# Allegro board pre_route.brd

Outline 330.2 x 304.8 mm; copper layers: TOP, L2_GND1, L3_IS1, L4_IS2, L5_PWR1, L6_IS3, L7_IS4, L8_GND2, L9_IS5, L10_IS6, L11_PWR2, L12_IS7, L13_IS8, L14_GND3, L15_IS9, L16_IS10, L17_PWR3, BOTTOM. Coordinates in mm from the lower left corner of the outline.
Outline path: 0,304.8 0,0 330.2,0 330.2,304.8 0,304.8

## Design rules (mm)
constraint set DEFAULT: min track width 0.127
net group BRIDGE_RXCLK_: nets BRIDGE_RXCLK_N BRIDGE_RXCLK_P
net group BRIDGE_TXCLK_: nets BRIDGE_TXCLK_N BRIDGE_TXCLK_P
net group DIFF_RX_DRSCLK_: nets DIFF_RX_DRSCLK_N DIFF_RX_DRSCLK_P
net group DIFF_RX_DRSTAT_0: nets DIFF_RX_DRSTAT_N0 DIFF_RX_DRSTAT_P0
net group DIFF_RX_DRSTAT_1: nets DIFF_RX_DRSTAT_N1 DIFF_RX_DRSTAT_P1
net group DIFF_RX_RCTL_: nets DIFF_RX_RCTL_N DIFF_RX_RCTL_P
net group DIFF_RX_RDCLK_: nets DIFF_RX_RDCLK_N DIFF_RX_RDCLK_P
net group DIFF_RX_RSTAT: nets DIFF_RX_RSTAT<0> DIFF_RX_RSTAT<1>
net group DIFF_TX_DTSCLK_: nets DIFF_TX_DTSCLK_N DIFF_TX_DTSCLK_P
net group DIFF_TX_DTSTAT_0: nets DIFF_TX_DTSTAT_N0 DIFF_TX_DTSTAT_P0
net group DIFF_TX_DTSTAT_1: nets DIFF_TX_DTSTAT_N1 DIFF_TX_DTSTAT_P1
net group DIFF_TX_TCTL_: nets DIFF_TX_TCTL_N DIFF_TX_TCTL_P
net group DIFF_TX_TDCLK_: nets DIFF_TX_TDCLK_N DIFF_TX_TDCLK_P
net group DIFF_TX_TSTAT: nets DIFF_TX_TSTAT<0> DIFF_TX_TSTAT<1>
net group DPA_RX_N: nets DPA_RX_N<0> DPA_RX_N<1>
net group DPA_RX_P: nets DPA_RX_P<0> DPA_RX_P<1>
net group DPA_TX_N: nets DPA_TX_N<0> DPA_TX_N<1>
net group DPA_TX_P: nets DPA_TX_P<0> DPA_TX_P<1>
net group DPACLK_IN_: nets DPACLK_IN_N DPACLK_IN_P
net group DPACLK_OUT_: nets DPACLK_OUT_N DPACLK_OUT_P
net group EXT_CLK_IN_: nets EXT_CLK_IN_N EXT_CLK_IN_P
net group LAN_RX: nets LAN_RXDN LAN_RXDP
net group LAN_TX: nets LAN_TXDN LAN_TXDP
net group PARALLELBUS_CLK_EN: nets PARALLELBUS_CLK_EN<0> PARALLELBUS_CLK_EN<1>
net group PARALLELBUS_ODT: nets PARALLELBUS_ODT<0> PARALLELBUS_ODT<1>
net group SMA_INPUT1_TO_SGX_: nets SMA_INPUT1_TO_SGX_N SMA_INPUT1_TO_SGX_P
net group SMA_INPUT2_TO_SGX_: nets SMA_INPUT2_TO_SGX_N SMA_INPUT2_TO_SGX_P
net group XCVR_RX_0C: nets XCVR_RX_N0C XCVR_RX_P0C
net group XCVR_RX_1C: nets XCVR_RX_N1C XCVR_RX_P1C
net group XCVR_RX_2C: nets XCVR_RX_N2C XCVR_RX_P2C
net group XCVR_RX_3C: nets XCVR_RX_N3C XCVR_RX_P3C
net group XCVR_RX_8C: nets XCVR_RX_N8C XCVR_RX_P8C
net group XCVR_RX_9C: nets XCVR_RX_N9C XCVR_RX_P9C
net group XCVR_RX_10C: nets XCVR_RX_N10C XCVR_RX_P10C
net group XCVR_RX_11C: nets XCVR_RX_N11C XCVR_RX_P11C
net group XCVR_RX_16C: nets XCVR_RX_N16C XCVR_RX_P16C
net group XCVR_RX_17C: nets XCVR_RX_N17C XCVR_RX_P17C
net group XCVR_RX_18C: nets XCVR_RX_N18C XCVR_RX_P18C
net group XCVR_RX_19C: nets XCVR_RX_N19C XCVR_RX_P19C
net group XTAL1_SGX_: nets XTAL1_SGX_N XTAL1_SGX_P
net group XTAL1_STX_: nets XTAL1_STX_N XTAL1_STX_P
net group XTAL2_SGX_: nets XTAL2_SGX_N XTAL2_SGX_P
net group XTAL2_STX_: nets XTAL2_STX_N XTAL2_STX_P
net group BRIDGE_RX_N: nets BRIDGE_RX_N<0> BRIDGE_RX_N<1> BRIDGE_RX_N<2> BRIDGE_RX_N<3> BRIDGE_RX_N<4> BRIDGE_RX_N<5> BRIDGE_RX_N<6> BRIDGE_RX_N<7> BRIDGE_RX_N<8> BRIDGE_RX_N<9> BRIDGE_RX_N<10> BRIDGE_RX_N<11> BRIDGE_RX_N<12> BRIDGE_RX_N<13> BRIDGE_RX_N<14> BRIDGE_RX_N<15>
net group BRIDGE_RX_P: nets BRIDGE_RX_P<0> BRIDGE_RX_P<1> BRIDGE_RX_P<2> BRIDGE_RX_P<3> BRIDGE_RX_P<4> BRIDGE_RX_P<5> BRIDGE_RX_P<6> BRIDGE_RX_P<7> BRIDGE_RX_P<8> BRIDGE_RX_P<9> BRIDGE_RX_P<10> BRIDGE_RX_P<11> BRIDGE_RX_P<12> BRIDGE_RX_P<13> BRIDGE_RX_P<14> BRIDGE_RX_P<15>
net group BRIDGE_TX_N: nets BRIDGE_TX_N<0> BRIDGE_TX_N<1> BRIDGE_TX_N<2> BRIDGE_TX_N<3> BRIDGE_TX_N<4> BRIDGE_TX_N<5> BRIDGE_TX_N<6> BRIDGE_TX_N<7> BRIDGE_TX_N<8> BRIDGE_TX_N<9> BRIDGE_TX_N<10> BRIDGE_TX_N<11> BRIDGE_TX_N<12> BRIDGE_TX_N<13> BRIDGE_TX_N<14> BRIDGE_TX_N<15>
net group BRIDGE_TX_P: nets BRIDGE_TX_P<0> BRIDGE_TX_P<1> BRIDGE_TX_P<2> BRIDGE_TX_P<3> BRIDGE_TX_P<4> BRIDGE_TX_P<5> BRIDGE_TX_P<6> BRIDGE_TX_P<7> BRIDGE_TX_P<8> BRIDGE_TX_P<9> BRIDGE_TX_P<10> BRIDGE_TX_P<11> BRIDGE_TX_P<12> BRIDGE_TX_P<13> BRIDGE_TX_P<14> BRIDGE_TX_P<15>
net group DEV2_D: nets DEV2_D<0> DEV2_D<1> DEV2_D<2> DEV2_D<3> DEV2_D<4> DEV2_D<5> DEV2_D<6> DEV2_D<7>
net group DIFF_PH: nets DATA_GEN_CLK_INN DATA_GEN_CLK_INP DIVIDE_BY_20_LVPECL_OUT_N DIVIDE_BY_20_LVPECL_OUT_P XTAL1_SGX_INT_N XTAL1_SGX_INT_P XTAL1_STX_INT_N XTAL1_STX_INT_P XTAL1_TP_N XTAL1_TP_P XTAL2_SGX_INT_N XTAL2_SGX_INT_P XTAL2_STX_INT_N XTAL2_STX_INT_P XTAL2_TP_N XTAL2_TP_P
net group DIFF_RX_N: nets DIFF_RX_N<0> DIFF_RX_N<1> DIFF_RX_N<2> DIFF_RX_N<3> DIFF_RX_N<4> DIFF_RX_N<5> DIFF_RX_N<6> DIFF_RX_N<7> DIFF_RX_N<8> DIFF_RX_N<9> DIFF_RX_N<10> DIFF_RX_N<11> DIFF_RX_N<12> DIFF_RX_N<13> DIFF_RX_N<14> DIFF_RX_N<15>
net group DIFF_RX_P: nets DIFF_RX_P<0> DIFF_RX_P<1> DIFF_RX_P<2> DIFF_RX_P<3> DIFF_RX_P<4> DIFF_RX_P<5> DIFF_RX_P<6> DIFF_RX_P<7> DIFF_RX_P<8> DIFF_RX_P<9> DIFF_RX_P<10> DIFF_RX_P<11> DIFF_RX_P<12> DIFF_RX_P<13> DIFF_RX_P<14> DIFF_RX_P<15>
net group DIFF_TX_N: nets DIFF_TX_N<0> DIFF_TX_N<1> DIFF_TX_N<2> DIFF_TX_N<3> DIFF_TX_N<4> DIFF_TX_N<5> DIFF_TX_N<6> DIFF_TX_N<7> DIFF_TX_N<8> DIFF_TX_N<9> DIFF_TX_N<10> DIFF_TX_N<11> DIFF_TX_N<12> DIFF_TX_N<13> DIFF_TX_N<14> DIFF_TX_N<15>
net group DIFF_TX_P: nets DIFF_TX_P<0> DIFF_TX_P<1> DIFF_TX_P<2> DIFF_TX_P<3> DIFF_TX_P<4> DIFF_TX_P<5> DIFF_TX_P<6> DIFF_TX_P<7> DIFF_TX_P<8> DIFF_TX_P<9> DIFF_TX_P<10> DIFF_TX_P<11> DIFF_TX_P<12> DIFF_TX_P<13> DIFF_TX_P<14> DIFF_TX_P<15>
net group FLASH_A: nets FLASH_A<0> FLASH_A<1> FLASH_A<2> FLASH_A<3> FLASH_A<4> FLASH_A<5> FLASH_A<6> FLASH_A<7> FLASH_A<8> FLASH_A<9> FLASH_A<10> FLASH_A<11> FLASH_A<12> FLASH_A<13> FLASH_A<14> FLASH_A<15> FLASH_A<16> FLASH_A<17> FLASH_A<18> FLASH_A<19> FLASH_A<20> FLASH_A<21>
net group FLASH_D: nets FLASH_D<0> FLASH_D<1> FLASH_D<2> FLASH_D<3> FLASH_D<4> FLASH_D<5> FLASH_D<6> FLASH_D<7> FLASH_D<8> FLASH_D<9> FLASH_D<10> FLASH_D<11> FLASH_D<12> FLASH_D<13> FLASH_D<14> FLASH_D<15>
net group GX_DIP: nets GX_DIP<0> GX_DIP<1> GX_DIP<2> GX_DIP<3> GX_DIP<4> GX_DIP<5> GX_DIP<6> GX_DIP<7>
net group GX_FLASH_A: nets GX_FLASH_A<0> GX_FLASH_A<1> GX_FLASH_A<2> GX_FLASH_A<3> GX_FLASH_A<4> GX_FLASH_A<5> GX_FLASH_A<6> GX_FLASH_A<7> GX_FLASH_A<8> GX_FLASH_A<9> GX_FLASH_A<10> GX_FLASH_A<11> GX_FLASH_A<12> GX_FLASH_A<13> GX_FLASH_A<14> GX_FLASH_A<15> GX_FLASH_A<16> GX_FLASH_A<17> GX_FLASH_A<18> GX_FLASH_A<19> GX_FLASH_A<20>
net group GX_FLASH_D: nets GX_FLASH_D<0> GX_FLASH_D<1> GX_FLASH_D<2> GX_FLASH_D<3> GX_FLASH_D<4> GX_FLASH_D<5> GX_FLASH_D<6> GX_FLASH_D<7> GX_FLASH_D<8> GX_FLASH_D<9> GX_FLASH_D<10> GX_FLASH_D<11> GX_FLASH_D<12> GX_FLASH_D<13> GX_FLASH_D<14> GX_FLASH_D<15>
net group GX_HEADER: nets GX_HEADER<0> GX_HEADER<1> GX_HEADER<2> GX_HEADER<3> GX_HEADER<4> GX_HEADER<5> GX_HEADER<6> GX_HEADER<7> GX_HEADER<8> GX_HEADER<9> GX_HEADER<10> GX_HEADER<11> GX_HEADER<12> GX_HEADER<13> GX_HEADER<14> GX_HEADER<15> GX_HEADER<16> GX_HEADER<17> GX_HEADER<18> GX_HEADER<19>
net group GX_LED: nets GX_LED<0> GX_LED<1> GX_LED<2> GX_LED<3> GX_LED<4> GX_LED<5>
net group GX_MICTOR_EP_: nets GX_MICTOR_EP_<0> GX_MICTOR_EP_<1> GX_MICTOR_EP_<2> GX_MICTOR_EP_<3> GX_MICTOR_EP_<4> GX_MICTOR_EP_<5> GX_MICTOR_EP_<6> GX_MICTOR_EP_<7> GX_MICTOR_EP_<8> GX_MICTOR_EP_<9> GX_MICTOR_EP_<10> GX_MICTOR_EP_<11> GX_MICTOR_EP_<12> GX_MICTOR_EP_<13> GX_MICTOR_EP_<14> GX_MICTOR_EP_<15>
net group GX_MICTOR_OP_: nets GX_MICTOR_OP_<0> GX_MICTOR_OP_<1> GX_MICTOR_OP_<2> GX_MICTOR_OP_<3> GX_MICTOR_OP_<4> GX_MICTOR_OP_<5> GX_MICTOR_OP_<6> GX_MICTOR_OP_<7> GX_MICTOR_OP_<8> GX_MICTOR_OP_<9> GX_MICTOR_OP_<10> GX_MICTOR_OP_<11> GX_MICTOR_OP_<12> GX_MICTOR_OP_<13> GX_MICTOR_OP_<14> GX_MICTOR_OP_<15>
net group GX_PB: nets GX_PB<0> GX_PB<1> GX_PB<2> GX_PB<3>
net group GX_RECOV_CLK: nets GX_RECOV_CLK<0> GX_RECOV_CLK<1> GX_RECOV_CLK<2> GX_RECOV_CLK<3> GX_RECOV_CLK<4>
net group GXPGM: nets GXPGM<0> GXPGM<1> GXPGM<2>
net group LAN_A: nets LAN_A<0> LAN_A<1> LAN_A<2> LAN_A<3> LAN_A<4> LAN_A<5> LAN_A<6> LAN_A<7> LAN_A<8> LAN_A<9> LAN_A<10> LAN_A<11> LAN_A<12> LAN_A<13> LAN_A<14>
net group LAN_BEN: nets LAN_BEN<0> LAN_BEN<1> LAN_BEN<2> LAN_BEN<3>
net group LAN_D: nets LAN_D<0> LAN_D<1> LAN_D<2> LAN_D<3> LAN_D<4> LAN_D<5> LAN_D<6> LAN_D<7> LAN_D<8> LAN_D<9> LAN_D<10> LAN_D<11> LAN_D<12> LAN_D<13> LAN_D<14> LAN_D<15> LAN_D<16> LAN_D<17> LAN_D<18> LAN_D<19> LAN_D<20> LAN_D<21> LAN_D<22> LAN_D<23> LAN_D<24> LAN_D<25> LAN_D<26> LAN_D<27> LAN_D<28> LAN_D<29> LAN_D<30> LAN_D<31>
net group PARALLELBUS_ADDR: nets PARALLELBUS_ADDR<0> PARALLELBUS_ADDR<1> PARALLELBUS_ADDR<2> PARALLELBUS_ADDR<3> PARALLELBUS_ADDR<4> PARALLELBUS_ADDR<5> PARALLELBUS_ADDR<6> PARALLELBUS_ADDR<7> PARALLELBUS_ADDR<8> PARALLELBUS_ADDR<9> PARALLELBUS_ADDR<10> PARALLELBUS_ADDR<11> PARALLELBUS_ADDR<12> PARALLELBUS_ADDR<13> PARALLELBUS_ADDR<14> PARALLELBUS_ADDR<15>
net group PARALLELBUS_BA: nets PARALLELBUS_BA<0> PARALLELBUS_BA<1> PARALLELBUS_BA<2>
net group PARALLELBUS_CB: nets PARALLELBUS_CB<0> PARALLELBUS_CB<1> PARALLELBUS_CB<2> PARALLELBUS_CB<3> PARALLELBUS_CB<4> PARALLELBUS_CB<5> PARALLELBUS_CB<6> PARALLELBUS_CB<7>
net group PARALLELBUS_DATA: nets PARALLELBUS_DATA<0> PARALLELBUS_DATA<1> PARALLELBUS_DATA<2> PARALLELBUS_DATA<3> PARALLELBUS_DATA<4> PARALLELBUS_DATA<5> PARALLELBUS_DATA<6> PARALLELBUS_DATA<7> PARALLELBUS_DATA<8> PARALLELBUS_DATA<9> PARALLELBUS_DATA<10> PARALLELBUS_DATA<11> PARALLELBUS_DATA<12> PARALLELBUS_DATA<13> PARALLELBUS_DATA<14> PARALLELBUS_DATA<15> PARALLELBUS_DATA<16> PARALLELBUS_DATA<17> PARALLELBUS_DATA<18> PARALLELBUS_DATA<19> PARALLELBUS_DATA<20> PARALLELBUS_DATA<21> PARALLELBUS_DATA<22> PARALLELBUS_DATA<23> PARALLELBUS_DATA<24> PARALLELBUS_DATA<25> PARALLELBUS_DATA<26> PARALLELBUS_DATA<27> PARALLELBUS_DATA<28> PARALLELBUS_DATA<29> PARALLELBUS_DATA<30> PARALLELBUS_DATA<31> PARALLELBUS_DATA<32> PARALLELBUS_DATA<33> PARALLELBUS_DATA<34> PARALLELBUS_DATA<35> PARALLELBUS_DATA<36> PARALLELBUS_DATA<37> PARALLELBUS_DATA<38> PARALLELBUS_DATA<39> PARALLELBUS_DATA<40> PARALLELBUS_DATA<41> PARALLELBUS_DATA<42> PARALLELBUS_DATA<43> PARALLELBUS_DATA<44> PARALLELBUS_DATA<45> PARALLELBUS_DATA<46> PARALLELBUS_DATA<47> PARALLELBUS_DATA<48> PARALLELBUS_DATA<49> PARALLELBUS_DATA<50> PARALLELBUS_DATA<51> PARALLELBUS_DATA<52> PARALLELBUS_DATA<53> PARALLELBUS_DATA<54> PARALLELBUS_DATA<55> PARALLELBUS_DATA<56> PARALLELBUS_DATA<57> PARALLELBUS_DATA<58> PARALLELBUS_DATA<59> PARALLELBUS_DATA<60> PARALLELBUS_DATA<61> PARALLELBUS_DATA<62> PARALLELBUS_DATA<63>
net group PARALLELBUS_DM: nets PARALLELBUS_DM<0> PARALLELBUS_DM<1> PARALLELBUS_DM<2> PARALLELBUS_DM<3> PARALLELBUS_DM<4> PARALLELBUS_DM<5> PARALLELBUS_DM<6> PARALLELBUS_DM<7> PARALLELBUS_DM<8>
net group PARALLELBUS_STROBE: nets PARALLELBUS_STROBE<0> PARALLELBUS_STROBE<1> PARALLELBUS_STROBE<2> PARALLELBUS_STROBE<3> PARALLELBUS_STROBE<4> PARALLELBUS_STROBE<5> PARALLELBUS_STROBE<6> PARALLELBUS_STROBE<7>
net group PMC_AD: nets PMC_AD<0> PMC_AD<1> PMC_AD<2> PMC_AD<3> PMC_AD<4> PMC_AD<5> PMC_AD<6> PMC_AD<7> PMC_AD<8> PMC_AD<9> PMC_AD<10> PMC_AD<11> PMC_AD<12> PMC_AD<13> PMC_AD<14> PMC_AD<15> PMC_AD<16> PMC_AD<17> PMC_AD<18> PMC_AD<19> PMC_AD<20> PMC_AD<21> PMC_AD<22> PMC_AD<23> PMC_AD<24> PMC_AD<25> PMC_AD<26> PMC_AD<27> PMC_AD<28> PMC_AD<29> PMC_AD<30> PMC_AD<31>
net group PMC_BUSMODEN: nets PMC_BUSMODEN<1> PMC_BUSMODEN<2> PMC_BUSMODEN<3> PMC_BUSMODEN<4>
net group PMC_C_BEN: nets PMC_C_BEN<0> PMC_C_BEN<1> PMC_C_BEN<2> PMC_C_BEN<3>
net group PWR_PH: nets 1.5V_A_INT 1.5V_GX_INT 1.5V_PLL 1.5V_PLL_B 1.5V_S_INT 1.5V_XCVR 1.5V_XCVR5 1.25V 2.5V 2.5V_DDR_VDD 2.5V_GX_IO 2.5V_OUT 2.5V_REG_IN 3.3V 3.3V_CLK1 3.3V_CLK2 3.3V_CLK3 3.3V_DIV 3.3V_EXT_CLK 3.3V_FAN_OUT 3.3V_LAN 3.3V_RS232 3.3V_S_IO 3.3V_S_IOB 3.3V_XCVR_CLKS 3.3VM 5VM 12VM -12VM -48V_IN -48V_ONN -48V_PWR BUS_CONV_5V GND GND_HSSI GND_PLL GND_RTN VCCA VCCQP
net group Q_SCRUZ_IO: nets Q_SCRUZ_IO<0> Q_SCRUZ_IO<1> Q_SCRUZ_IO<2> Q_SCRUZ_IO<3> Q_SCRUZ_IO<4> Q_SCRUZ_IO<5> Q_SCRUZ_IO<6> Q_SCRUZ_IO<7> Q_SCRUZ_IO<8> Q_SCRUZ_IO<9> Q_SCRUZ_IO<10> Q_SCRUZ_IO<11> Q_SCRUZ_IO<12> Q_SCRUZ_IO<13> Q_SCRUZ_IO<14> Q_SCRUZ_IO<15> Q_SCRUZ_IO<16> Q_SCRUZ_IO<17> Q_SCRUZ_IO<18> Q_SCRUZ_IO<19> Q_SCRUZ_IO<20> Q_SCRUZ_IO<21> Q_SCRUZ_IO<22> Q_SCRUZ_IO<23> Q_SCRUZ_IO<24> Q_SCRUZ_IO<25> Q_SCRUZ_IO<26> Q_SCRUZ_IO<27> Q_SCRUZ_IO<28> Q_SCRUZ_IO<29> Q_SCRUZ_IO<30> Q_SCRUZ_IO<31> Q_SCRUZ_IO<32> Q_SCRUZ_IO<33> Q_SCRUZ_IO<34> Q_SCRUZ_IO<35> Q_SCRUZ_IO<36> Q_SCRUZ_IO<37> Q_SCRUZ_IO<38> Q_SCRUZ_IO<39>
net group S_DIP: nets S_DIP<0> S_DIP<1> S_DIP<2> S_DIP<3> S_DIP<4> S_DIP<5> S_DIP<6> S_DIP<7>
net group S_HEADER: nets S_HEADER<0> S_HEADER<1> S_HEADER<2> S_HEADER<3> S_HEADER<4> S_HEADER<5> S_HEADER<6> S_HEADER<7> S_HEADER<8> S_HEADER<9> S_HEADER<10> S_HEADER<11> S_HEADER<12> S_HEADER<13> S_HEADER<14> S_HEADER<15> S_HEADER<16> S_HEADER<17> S_HEADER<18> S_HEADER<19>
net group S_LED: nets S_LED<0> S_LED<1> S_LED<2> S_LED<3> S_LED<4> S_LED<5>
net group S_MICTOR_EP_: nets S_MICTOR_EP_<0> S_MICTOR_EP_<1> S_MICTOR_EP_<2> S_MICTOR_EP_<3> S_MICTOR_EP_<4> S_MICTOR_EP_<5> S_MICTOR_EP_<6> S_MICTOR_EP_<7> S_MICTOR_EP_<8> S_MICTOR_EP_<9> S_MICTOR_EP_<10> S_MICTOR_EP_<11> S_MICTOR_EP_<12> S_MICTOR_EP_<13> S_MICTOR_EP_<14> S_MICTOR_EP_<15>
net group S_MICTOR_OP_: nets S_MICTOR_OP_<0> S_MICTOR_OP_<1> S_MICTOR_OP_<2> S_MICTOR_OP_<3> S_MICTOR_OP_<4> S_MICTOR_OP_<5> S_MICTOR_OP_<6> S_MICTOR_OP_<7> S_MICTOR_OP_<8> S_MICTOR_OP_<9> S_MICTOR_OP_<10> S_MICTOR_OP_<11> S_MICTOR_OP_<12> S_MICTOR_OP_<13> S_MICTOR_OP_<14> S_MICTOR_OP_<15>
net group S_PB: nets S_PB<0> S_PB<1> S_PB<2> S_PB<3>
net group SCRUZ_IO: nets SCRUZ_IO<0> SCRUZ_IO<1> SCRUZ_IO<2> SCRUZ_IO<3> SCRUZ_IO<4> SCRUZ_IO<5> SCRUZ_IO<6> SCRUZ_IO<7> SCRUZ_IO<8> SCRUZ_IO<9> SCRUZ_IO<10> SCRUZ_IO<11> SCRUZ_IO<12> SCRUZ_IO<13> SCRUZ_IO<14> SCRUZ_IO<15> SCRUZ_IO<16> SCRUZ_IO<17> SCRUZ_IO<18> SCRUZ_IO<19> SCRUZ_IO<20> SCRUZ_IO<21> SCRUZ_IO<22> SCRUZ_IO<23> SCRUZ_IO<24> SCRUZ_IO<25> SCRUZ_IO<26> SCRUZ_IO<27> SCRUZ_IO<28> SCRUZ_IO<29> SCRUZ_IO<30> SCRUZ_IO<31> SCRUZ_IO<32> SCRUZ_IO<33> SCRUZ_IO<34> SCRUZ_IO<35> SCRUZ_IO<36> SCRUZ_IO<37> SCRUZ_IO<38> SCRUZ_IO<39>
net group SFP0_MOD_DEF4_: nets SFP0_MOD_DEF4_<0> SFP0_MOD_DEF4_<1> SFP0_MOD_DEF4_<2>
net group SFP1_MOD_DEF5_: nets SFP1_MOD_DEF5_<0> SFP1_MOD_DEF5_<1> SFP1_MOD_DEF5_<2>
net group SFP2_MOD_DEF6_: nets SFP2_MOD_DEF6_<0> SFP2_MOD_DEF6_<1> SFP2_MOD_DEF6_<2>
net group SFP3_MOD_DEF7_: nets SFP3_MOD_DEF7_<0> SFP3_MOD_DEF7_<1> SFP3_MOD_DEF7_<2>
net group XCVR_RX_N: nets XCVR_RX_N<0> XCVR_RX_N<1> XCVR_RX_N<2> XCVR_RX_N<3> XCVR_RX_N<4> XCVR_RX_N<5> XCVR_RX_N<6> XCVR_RX_N<7> XCVR_RX_N<8> XCVR_RX_N<9> XCVR_RX_N<10> XCVR_RX_N<11> XCVR_RX_N<12> XCVR_RX_N<13> XCVR_RX_N<14> XCVR_RX_N<15> XCVR_RX_N<16> XCVR_RX_N<17> XCVR_RX_N<18> XCVR_RX_N<19>
net group XCVR_RX_P: nets XCVR_RX_P<0> XCVR_RX_P<1> XCVR_RX_P<2> XCVR_RX_P<3> XCVR_RX_P<4> XCVR_RX_P<5> XCVR_RX_P<6> XCVR_RX_P<7> XCVR_RX_P<8> XCVR_RX_P<9> XCVR_RX_P<10> XCVR_RX_P<11> XCVR_RX_P<12> XCVR_RX_P<13> XCVR_RX_P<14> XCVR_RX_P<15> XCVR_RX_P<16> XCVR_RX_P<17> XCVR_RX_P<18> XCVR_RX_P<19>
net group XCVR_TX_N: nets XCVR_TX_N<0> XCVR_TX_N<1> XCVR_TX_N<2> XCVR_TX_N<3> XCVR_TX_N<4> XCVR_TX_N<5> XCVR_TX_N<6> XCVR_TX_N<7> XCVR_TX_N<8> XCVR_TX_N<9> XCVR_TX_N<10> XCVR_TX_N<11> XCVR_TX_N<12> XCVR_TX_N<13> XCVR_TX_N<14> XCVR_TX_N<15> XCVR_TX_N<16> XCVR_TX_N<17> XCVR_TX_N<18> XCVR_TX_N<19>
net group XCVR_TX_P: nets XCVR_TX_P<0> XCVR_TX_P<1> XCVR_TX_P<2> XCVR_TX_P<3> XCVR_TX_P<4> XCVR_TX_P<5> XCVR_TX_P<6> XCVR_TX_P<7> XCVR_TX_P<8> XCVR_TX_P<9> XCVR_TX_P<10> XCVR_TX_P<11> XCVR_TX_P<12> XCVR_TX_P<13> XCVR_TX_P<14> XCVR_TX_P<15> XCVR_TX_P<16> XCVR_TX_P<17> XCVR_TX_P<18> XCVR_TX_P<19>
net group XPAK_PRTAD: nets XPAK_PRTAD<0> XPAK_PRTAD<1> XPAK_PRTAD<2> XPAK_PRTAD<3> XPAK_PRTAD<4>
net group XPAK_VEND: nets XPAK_VEND<0> XPAK_VEND<1> XPAK_VEND<2> XPAK_VEND<3>

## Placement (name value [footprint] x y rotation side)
C1  0.01uf  [CAP_0402]  -102.35 126.37 0 top
C2  0.01uf  [CAP_0402]  -102.35 137.8 0 top
C3  0.01uf  [CAP_0402]  -102.35 149.23 0 top
C4  0.01uf  [CAP_0402]  -102.35 151.52 0 top
C5  0.01uf  [CAP_0402]  -102.35 153.8 0 top
C6  0.01uf  [CAP_0402]  -102.35 156.09 0 top
C7  0.01uf  [CAP_0402]  -102.35 158.38 0 top
C8  0.01uf  [CAP_0402]  -102.35 162.95 0 top
C9  10uf  [CAP_1206]  -70.12 156.4 0 top
C10  0.01uf  [CAP_0402]  -102.35 165.23 0 top
C11  0.01uf  [CAP_0402]  -102.35 167.52 0 top
C12  10uf  [CAPT_3528]  -55.19 31.98 0 top
C13  0.1uf  [CAP_0603]  -157.01 221.32 0 top
C14  10uf  [CAP_1206]  -70.12 182.84 0 top
C15  10uf  [CAP_1206]  -70.12 177.55 0 top
C16  0.1uf  [CAP_0603]  -157.01 192.07 0 top
C17  0.01uf  [CAP_0402]  -102.35 169.81 0 top
C18  0.01uf  [CAP_0402]  -102.35 172.09 0 top
C19  220uf  [CAPT_7343]  -84.03 68.71 0 top
C20  0.01uf  [CAP_0402]  -102.35 140.09 0 top
C21  0.01uf  [CAP_0402]  -102.35 142.37 0 top
C22  0.01uf  [CAP_0402]  -102.35 174.38 0 top
C23  0.01uf  [CAP_0402]  -102.35 176.66 0 top
C24  0.01uf  [CAP_0402]  -102.35 144.66 0 top
C25  0.01uf  [CAP_0402]  -102.35 146.95 0 top
C26  0.01uf  [CAP_0603]  -76.05 229.73 0 top
C27  0.01uf  [CAP_0603]  -76.05 200.48 0 top
C28  820pf  [CAP_SP]  -84.55 43.56 0 top
C29  0.01uf  [CAP_0402]  -102.35 178.95 0 top
C30  0.01uf  [CAP_0402]  -79.57 7.35 0 top
C31  0.01uf  [CAP_0402]  -79.57 5.06 0 top
C32  0.01uf  [CAP_0402]  -102.35 181.24 0 top
C33  0.01uf  [CAP_0603]  -76.05 131.02 0 top
C34  0.01uf  [CAP_0603]  -76.05 105.43 0 top
C35  0.01uf  [CAP_0603]  -76.05 87.15 0 top
C36  0.01uf  [CAP_0603]  -76.05 72.53 0 top
C37  0.01uf  [CAP_0603]  -76.05 61.56 0 top
C38  0.01uf  [CAP_0603]  -76.05 43.28 0 top
C39  0.01uf  [CAP_0603]  -76.05 17.69 0 top
C40  0.01uf  [CAP_0603]  -77.9 295.53 0 top
C41  2.2uf  [CAP_0805]  -70.02 245.08 0 top
C42  680uf  [CAP_SP]  -95.94 268.88 0 top
C43  0.01uf  [CAP_0603]  -77.9 258.98 0 top
C44  0.1uf  [CAP_0603]  -51.09 145.64 0 top
C45  0.1uf  [CAP_0603]  -51.09 138.33 0 top
C46  0.01uf  [CAP_0603]  -77.9 200.48 0 top
C47  2.2uf  [CAP_0805]  -70.02 208.09 0 top
C48  0.047uf  [CAP_1206]  -91.56 256.54 0 top
C49  0.01uf  [CAP_0603]  -77.9 156.61 0 top
C50  10uf  [CAPT_3528]  -55.19 27.67 0 top
C51  10uf  [CAPT_3528]  -55.19 23.35 0 top
C52  10uf  [CAPT_3528]  -55.19 19.03 0 top
C53  10uf  [CAPT_3528]  -55.19 14.71 0 top
C54  0.1uf  [CAP_0603]  -51.09 3.07 0 top
C55  0.1uf  [CAP_0603]  -52.94 291.88 0 top
C56  0.01uf  [CAP_0603]  -77.9 30.03 0 top
C57  680uf  [CAP_SP]  -95.94 249.19 0 top
C58  0.01uf  [CAP_0603]  -79.75 288.22 0 top
C59  0.01uf  [CAP_0603]  -79.75 269.94 0 top
C60  10uf  [CAPT_3528]  -55.19 10.39 0 top
C61  0.01uf  [CAP_0603]  -79.75 229.73 0 top
C62  0.047uf  [CAP_0603]  -91.14 237.66 0 top
C63  0.047uf  [CAP_0603]  -91.14 234.01 0 top
C64  0.047uf  [CAP_0603]  -91.14 230.35 0 top
C65  0.047uf  [CAP_0603]  -91.14 226.7 0 top
C66  0.01uf  [CAP_0603]  -79.75 152.96 0 top
C67  0.01uf  [CAP_0603]  -79.75 149.3 0 top
C68  0.01uf  [CAP_0603]  -79.75 145.64 0 top
C69  0.01uf  [CAP_0603]  -79.75 141.99 0 top
C70  0.01uf  [CAP_0603]  -79.75 138.33 0 top
C71  0.01uf  [CAP_0603]  -79.75 134.68 0 top
C72  10uf  [CAPT_3528]  -61.54 289.56 0 top
C73  820pf  [CAP_SP]  -84.55 29.16 0 top
C74  0.01uf  [CAP_0603]  -79.75 120.05 0 top
C75  0.01uf  [CAP_0603]  -79.75 116.4 0 top
C76  0.01uf  [CAP_0603]  -79.75 112.74 0 top
C77  10uf  [CAPT_3528]  -61.54 285.24 0 top
C78  0.01uf  [CAP_0603]  -79.75 109.09 0 top
C79  0.01uf  [CAP_0603]  -79.75 105.43 0 top
C80  10uf  [CAPT_3528]  -61.54 280.92 0 top
C81  6200pf  [CAP_0603]  -102.53 268.11 0 top
C82  120pf  [CAP_0603]  -102.53 264.45 0 top
C83  0.01uf  [CAP_0402]  -102.35 261.48 0 top
C84  0.1uf  [CAP_0603]  -52.94 79.84 0 top
C85  0.01uf  [CAP_0603]  -79.75 101.77 0 top
C86  10uf  [CAP_1206]  -70.12 161.69 0 top
C87  0.1uf  [CAP_0603]  -79.75 13.98 0 top
C88  0.001uf  [CAP_0402]  -102.35 259.2 0 top
C89  0.1uf  [CAP_0603]  -52.94 76.18 0 top
C90  0.1uf  [CAP_0603]  -79.75 10.32 0 top
C91  0.01uf  [CAP_0603]  -79.75 98.12 0 top
C92  0.1uf  [CAP_0603]  -52.94 72.53 0 top
C93  1.0uf  [CAP_0805]  -102.85 253.71 0 top
C94  0.001uf  [CAP_0402]  -102.35 256.91 0 top
C95  10uf  [CAP_1206]  -70.12 151.11 0 top
C96  0.001uf  [CAP_0402]  -102.35 248.23 0 top
C97  0.001uf  [CAP_0402]  -102.35 250.52 0 top
C98  0.001uf  [CAP_0402]  -69.52 85.22 0 top
C99  0.001uf  [CAP_0402]  -156.83 224.29 0 top
C100  0.1uf  [CAP_1206]  -102.95 185.02 0 top
C101  0.01uf  [CAP_0402]  -102.35 128.66 0 top
C102  0.1uf  [CAP_0603]  -102.53 189.5 0 top
C103  0.01uf  [CAP_0603]  -102.53 204.12 0 top
C104  0.01uf  [CAP_0402]  -102.35 130.94 0 top
C105  0.01uf  [CAP_0402]  -102.35 133.23 0 top
C106  0.001uf  [CAP_0402]  -77.72 80.52 0 top
C107  0.001uf  [CAP_0402]  -69.52 87.5 0 top
C108  0.001uf  [CAP_0402]  -102.35 229.94 0 top
C109  0.001uf  [CAP_0402]  -102.35 232.23 0 top
C110  0.1uf  [CAP_0603]  -157.01 217.66 0 top
C111  0.1uf  [CAP_0603]  -52.94 68.87 0 top
C112  0.1uf  [CAP_0603]  -52.94 65.22 0 top
C113  0.1uf  [CAP_0603]  -52.94 61.56 0 top
C114  0.1uf  [CAP_0603]  -52.94 57.91 0 top
C115  0.01uf  [CAP_0402]  -102.35 135.52 0 top
C116  0.1uf  [CAP_0603]  -52.94 54.25 0 top
C117  0.1uf  [CAP_0603]  -52.94 50.59 0 top
C118  0.1uf  [CAP_0603]  -52.94 46.94 0 top
C119  0.1uf  [CAP_0603]  -52.94 43.28 0 top
C120  0.1uf  [CAP_0603]  -59.29 276.94 0 top
C121  47uf  [CAPT_7343]  -63.57 250.25 0 top
C122  0.1uf  [CAP_0603]  -59.29 273.28 0 top
C123  47uf  [CAPT_7343]  -63.57 244.41 0 top
C124  0.1uf  [CAP_1206]  -59.71 238.85 0 top
C126  1uf  [CAP_0805]  -59.61 234.15 0 top
C128  1uf  [CAP_0805]  -59.61 230.04 0 top
C129  0.01uf  [CAP_0603]  -59.29 213.82 0 top
C130  0.001uf  [CAP_0603]  -59.29 137.05 0 top
C131  33uf  [CAPT_7343]  -63.57 48.22 0 top
C132  0.001uf  [CAP_0603]  -59.29 133.4 0 top
C133  100pf  [CAP_0603]  -59.29 43.47 0 top
C134  0.1uf  [CAP_0603]  -157.01 214.01 0 top
C135  0.1uf  [CAP_0603]  -59.29 39.81 0 top
C136  2.2uf  [CAP_0805]  -59.61 14 0 top
C137  2.2uf  [CAP_0805]  -59.61 9.89 0 top
C138  2.2uf  [CAP_0805]  -59.61 5.78 0 top
C139  2.2uf  [CAP_0805]  -70.02 302.62 0 top
C140  0.01uf  [CAP_0603]  -59.29 210.17 0 top
C141  0.1uf  [CAP_0603]  -59.29 36.16 0 top
C142  0.001uf  [CAP_0603]  -59.29 129.74 0 top
C143  0.1uf  [CAP_0603]  -157.01 203.04 0 top
C144  0.01uf  [CAP_0603]  -59.29 206.51 0 top
C145  47uf  [CAPT_3528]  -71.95 146.3 0 top
C146  47uf  [CAPT_3528]  -71.95 141.99 0 top
C147  0.1uf  [CAP_0603]  -157.01 210.35 0 top
C148  0.1uf  [CAP_0603]  -157.01 206.7 0 top
C149  0.01uf  [CAP_0603]  -69.7 138 0 top
C150  0.01uf  [CAP_0603]  -69.7 134.34 0 top
C151  0.01uf  [CAP_0603]  -69.7 130.69 0 top
C152  0.01uf  [CAP_0603]  -69.7 127.03 0 top
C153  0.01uf  [CAP_0603]  -69.7 123.38 0 top
C154  0.01uf  [CAP_0603]  -69.7 119.72 0 top
C155  0.01uf  [CAP_0603]  -69.7 116.06 0 top
C156  0.01uf  [CAP_0603]  -69.7 112.41 0 top
C157  0.01uf  [CAP_0603]  -69.7 108.75 0 top
C158  0.01uf  [CAP_0603]  -69.7 105.1 0 top
C159  0.01uf  [CAP_0603]  -69.7 101.44 0 top
C160  0.01uf  [CAP_0603]  -69.7 97.79 0 top
C161  0.01uf  [CAP_0603]  -69.7 94.13 0 top
C162  0.01uf  [CAP_0603]  -69.7 90.47 0 top
C163  0.01uf  [CAP_0603]  -102.53 223.32 0 top
C164  0.01uf  [CAP_0603]  -77.9 83.5 0 top
C165  0.1uf  [CAP_0603]  -157.01 199.38 0 top
C166  0.01uf  [CAP_0603]  -102.53 226.97 0 top
C167  1.0uf  [CAP_0805]  -80.07 90.13 0 top
C168  0.001uf  [CAP_0603]  -59.29 126.08 0 top
C169  0.1uf  [CAP_0603]  -59.29 32.5 0 top
C170  0.01uf  [CAP_0603]  -69.7 78.59 0 top
C171  0.1uf  [CAP_0603]  -157.01 195.73 0 top
C172  0.1uf  [CAP_0603]  -157.01 173.79 0 top
C173  0.01uf  [CAP_0603]  -69.7 74.93 0 top
C174  0.1uf  [CAP_0603]  -157.01 188.42 0 top
C175  0.01uf  [CAP_0603]  -69.7 71.28 0 top
C176  0.1uf  [CAP_0603]  -157.01 184.76 0 top
C177  0.01uf  [CAP_0603]  -69.7 67.62 0 top
C178  0.1uf  [CAP_0603]  -157.01 181.11 0 top
C179  0.01uf  [CAP_0603]  -69.7 63.97 0 top
C180  0.1uf  [CAP_0603]  -157.01 177.45 0 top
C181  0.01uf  [CAP_0603]  -69.7 60.31 0 top
C182  0.1uf  [CAP_0603]  -157.01 151.86 0 top
C183  0.1uf  [CAP_0603]  -157.01 170.14 0 top
C184  0.01uf  [CAP_0603]  -69.7 56.66 0 top
C185  0.01uf  [CAP_0603]  -69.7 53 0 top
C186  0.1uf  [CAP_0603]  -157.01 166.48 0 top
C187  0.01uf  [CAP_0603]  -69.7 49.34 0 top
C188  0.1uf  [CAP_0603]  -157.01 162.83 0 top
C189  0.01uf  [CAP_0603]  -69.7 45.69 0 top
C190  0.01uf  [CAP_0603]  -69.7 42.03 0 top
C191  0.01uf  [CAP_0603]  -69.7 38.38 0 top
C192  0.01uf  [CAP_0603]  -69.7 34.72 0 top
C193  0.01uf  [CAP_0603]  -69.7 31.06 0 top
C194  0.01uf  [CAP_0603]  -69.7 27.41 0 top
C195  0.01uf  [CAP_0603]  -69.7 23.75 0 top
C196  0.1uf  [CAP_0603]  -157.01 159.17 0 top
C197  0.1uf  [CAP_0603]  -157.01 155.52 0 top
C198  0.1uf  [CAP_0603]  -157.01 115.3 0 top
C199  0.01uf  [CAP_0603]  -69.7 20.1 0 top
C200  0.01uf  [CAP_0603]  -69.7 16.44 0 top
C201  0.01uf  [CAP_0603]  -69.7 12.79 0 top
C202  0.01uf  [CAP_0603]  -59.29 202.86 0 top
C203  0.01uf  [CAP_0603]  -59.29 199.2 0 top
C204  0.01uf  [CAP_0603]  -69.7 9.13 0 top
C205  0.1uf  [CAP_0603]  -157.01 148.2 0 top
C206  2.2uf  [CAP_0805]  -70.02 298.51 0 top
C207  2.2uf  [CAP_0805]  -70.02 294.4 0 top
C208  0.001uf  [CAP_0603]  -59.29 122.43 0 top
C209  47uf  [CAPT_7343]  -84.03 57.03 0 top
C210  220uf  [CAPT_7343]  -84.03 62.87 0 top
C211  0.01uf  [CAP_0603]  -69.7 5.47 0 top
C212  0.01uf  [CAP_0603]  -69.7 1.82 0 top
C213  0.01uf  [CAP_0603]  -76.05 302.85 0 top
C214  0.1uf  [CAP_0603]  -157.01 144.55 0 top
C215  0.01uf  [CAP_0603]  -76.05 299.19 0 top
C216  0.01uf  [CAP_0603]  -76.05 295.53 0 top
C217  0.01uf  [CAP_0603]  -76.05 291.88 0 top
C218  0.1uf  [CAP_0603]  -157.01 140.89 0 top
C219  0.01uf  [CAP_0603]  -76.05 288.22 0 top
C220  0.1uf  [CAP_0603]  -157.01 137.24 0 top
C226  0.1uf  [CAP_0603]  -157.01 133.58 0 top
C227  0.01uf  [CAP_0603]  -76.05 284.57 0 top
C228  0.1uf  [CAP_0603]  -157.01 129.92 0 top
C229  2.2uf  [CAP_0805]  -70.02 290.29 0 top
C230  0.1uf  [CAP_0603]  -157.01 126.27 0 top
C231  2.2uf  [CAP_0805]  -70.02 286.18 0 top
C232  1.0uf  [CAP_0805]  -80.07 86.02 0 top
C233  0.001uf  [CAP_0603]  -59.29 118.77 0 top
C234  0.01uf  [CAP_0603]  -59.29 195.54 0 top
C235  0.01uf  [CAP_0603]  -76.05 280.91 0 top
C236  2.2uf  [CAP_0805]  -70.02 282.07 0 top
C237  0.1uf  [CAP_0603]  -59.29 28.85 0 top
C238  0.1uf  [CAP_0603]  -157.01 122.61 0 top
C239  0.1uf  [CAP_0603]  -157.01 118.96 0 top
C240  0.1uf  [CAP_0603]  -158.31 69.28 0 top
C241  0.01uf  [CAP_0603]  -76.05 277.25 0 top
C242  0.01uf  [CAP_0603]  -59.29 191.89 0 top
C243  0.01uf  [CAP_0603]  -76.05 273.6 0 top
C244  0.01uf  [CAP_0603]  -76.05 269.94 0 top
C245  0.01uf  [CAP_0603]  -76.05 266.29 0 top
C246  0.01uf  [CAP_0603]  -76.05 262.63 0 top
C247  0.1uf  [CAP_0603]  -157.01 111.65 0 top
C248  0.01uf  [CAP_0603]  -76.05 258.98 0 top
C249  0.1uf  [CAP_0603]  -157.01 107.99 0 top
C250  0.01uf  [CAP_0603]  -76.05 255.32 0 top
C251  0.01uf  [CAP_0603]  -76.05 251.66 0 top
C252  0.01uf  [CAP_0603]  -76.05 248.01 0 top
C253  0.01uf  [CAP_0603]  -76.05 244.35 0 top
C254  0.01uf  [CAP_0603]  -76.05 240.7 0 top
C255  0.01uf  [CAP_0603]  -76.05 237.04 0 top
C256  0.1uf  [CAP_0603]  -157.01 104.33 0 top
C257  0.1uf  [CAP_0603]  -157.01 100.68 0 top
C258  0.01uf  [CAP_0603]  -76.05 233.38 0 top
C259  0.001uf  [CAP_0603]  -59.29 115.12 0 top
C260  0.01uf  [CAP_0603]  -76.05 226.07 0 top
C261  0.1uf  [CAP_0603]  -157.01 97.02 0 top
C262  0.01uf  [CAP_0603]  -76.05 222.42 0 top
C263  0.001uf  [CAP_0603]  -59.29 111.46 0 top
C264  0.01uf  [CAP_0603]  -76.05 218.76 0 top
C265  0.01uf  [CAP_0603]  -76.05 215.11 0 top
C266  0.01uf  [CAP_0603]  -59.29 188.23 0 top
C267  0.01uf  [CAP_0603]  -76.05 211.45 0 top
C268  0.01uf  [CAP_0603]  -76.05 207.79 0 top
C269  0.01uf  [CAP_0603]  -76.05 204.14 0 top
C270  0.01uf  [CAP_0603]  -59.29 184.58 0 top
C271  0.01uf  [CAP_0603]  -76.05 196.83 0 top
C272  0.01uf  [CAP_0603]  -76.05 193.17 0 top
C273  0.1uf  [CAP_0603]  -157.01 93.37 0 top
C274  0.1uf  [CAP_0603]  -157.01 89.71 0 top
C275  0.01uf  [CAP_0603]  -76.05 189.51 0 top
C276  0.1uf  [CAP_0603]  -157.01 86.05 0 top
C277  0.1uf  [CAP_0603]  -157.01 82.4 0 top
C278  0.01uf  [CAP_0603]  -76.05 185.86 0 top
C279  0.1uf  [CAP_0603]  -157.01 78.74 0 top
C280  0.1uf  [CAP_0603]  -79.75 17.63 0 top
C281  0.01uf  [CAP_0603]  -76.05 182.2 0 top
C282  0.1uf  [CAP_0603]  -158.18 72.83 0 top
C283  0.1uf  [CAP_0603]  -51.09 291.88 0 top
C284  0.1uf  [CAP_0603]  -158.31 65.98 0 top
C285  0.01uf  [CAP_0603]  -76.05 178.55 0 top
C286  0.01uf  [CAP_0603]  -76.05 174.89 0 top
C287  0.1uf  [CAP_0603]  -158.43 62.23 0 top
C288  0.1uf  [CAP_0603]  -158.69 58.67 0 top
C289  0.01uf  [CAP_0603]  -76.05 171.24 0 top
C290  0.1uf  [CAP_0603]  -158.56 54.8 0 top
C291  0.001uf  [CAP_0603]  -59.29 107.81 0 top
C292  0.001uf  [CAP_0603]  -59.29 104.15 0 top
C293  0.01uf  [CAP_0603]  -76.05 167.58 0 top
C294  0.1uf  [CAP_0603]  -158.69 51.12 0 top
C295  0.1uf  [CAP_0603]  -158.69 47.62 0 top
C296  0.1uf  [CAP_0603]  -158.81 43.94 0 top
C297  0.1uf  [CAP_0603]  -159.36 37.23 0 top
C298  0.1uf  [CAP_0603]  -159.36 33.58 0 top
C299  0.01uf  [CAP_0603]  -59.29 180.92 0 top
C300  0.01uf  [CAP_0603]  -59.29 177.27 0 top
C301  0.1uf  [CAP_0603]  -159.36 29.92 0 top
C302  0.1uf  [CAP_0603]  -159.36 26.26 0 top
C303  2.2uf  [CAP_0805]  -70.02 277.96 0 top
C304  0.01uf  [CAP_0603]  -76.05 163.92 0 top
C305  0.01uf  [CAP_0603]  -76.05 160.27 0 top
C306  0.01uf  [CAP_0603]  -76.05 156.61 0 top
C307  100pf  [CAP_0402]  -90.96 298.96 0 top
C308  0.1uf  [CAP_0402]  -90.96 296.67 0 top
C309  0.01uf  [CAP_0603]  -76.05 152.96 0 top
C310  0.1uf  [CAP_0603]  -159.36 22.61 0 top
C311  0.1uf  [CAP_0603]  -159.36 18.95 0 top
C312  0.1uf  [CAP_0603]  -159.36 15.3 0 top
C313  1.0uf  [CAP_0805]  -80.07 81.91 0 top
C314  2.2uf  [CAP_0805]  -70.02 273.85 0 top
C315  0.1uf  [CAP_0603]  -159.36 11.64 0 top
C316  0.01uf  [CAP_0603]  -76.05 149.3 0 top
C317  0.1uf  [CAP_0402]  -90.96 294.39 0 top
C318  0.01uf  [CAP_0603]  -76.05 145.64 0 top
C319  0.1uf  [CAP_0603]  -159.36 7.99 0 top
C320  0.01uf  [CAP_0603]  -76.05 141.99 0 top
C321  0.01uf  [CAP_0603]  -76.05 138.33 0 top
C322  0.01uf  [CAP_0603]  -76.05 134.68 0 top
C323  0.1uf  [CAP_0603]  -159.36 4.33 0 top
C324  0.001uf  [CAP_0603]  -59.29 100.49 0 top
C325  0.1uf  [CAP_0603]  -51.09 302.85 0 top
C326  0.1uf  [CAP_0603]  -51.09 299.19 0 top
C327  0.1uf  [CAP_0603]  -51.09 295.53 0 top
C328  0.1uf  [CAP_0402]  -90.96 292.1 0 top
C329  2.2uf  [CAP_0805]  -70.02 269.74 0 top
C330  0.01uf  [CAP_0603]  -76.05 127.37 0 top
C331  0.1uf  [CAP_0603]  -59.29 25.19 0 top
C332  0.01uf  [CAP_0603]  -59.29 173.61 0 top
C333  0.01uf  [CAP_0603]  -76.05 123.71 0 top
C334  0.01uf  [CAP_0603]  -76.05 120.05 0 top
C335  0.01uf  [CAP_0603]  -76.05 116.4 0 top
C336  0.1uf  [CAP_0603]  -51.09 204.14 0 top
C337  0.01uf  [CAP_0603]  -76.05 112.74 0 top
C338  0.1uf  [CAP_0603]  -51.09 288.22 0 top
C339  0.01uf  [CAP_0603]  -76.05 109.09 0 top
C340  0.1uf  [CAP_0603]  -51.09 284.57 0 top
C341  0.001uf  [CAP_0603]  -59.29 96.84 0 top
C342  0.1uf  [CAP_0603]  -51.09 280.91 0 top
C343  0.01uf  [CAP_0603]  -76.05 101.77 0 top
C344  0.01uf  [CAP_0603]  -76.05 98.12 0 top
C345  0.1uf  [CAP_0603]  -51.09 277.25 0 top
C346  0.01uf  [CAP_0603]  -76.05 94.46 0 top
C347  0.1uf  [CAP_0603]  -51.09 273.6 0 top
C348  0.1uf  [CAP_0603]  -51.09 269.94 0 top
C349  0.01uf  [CAP_0603]  -76.05 90.81 0 top
C350  0.1uf  [CAP_0603]  -59.29 21.54 0 top
C351  0.1uf  [CAP_0603]  -51.09 266.29 0 top
C352  0.1uf  [CAP_0603]  -51.09 262.63 0 top
C353  0.01uf  [CAP_0603]  -76.05 83.5 0 top
C354  0.1uf  [CAP_0603]  -51.09 258.98 0 top
C355  0.01uf  [CAP_0603]  -76.05 79.84 0 top
C356  0.01uf  [CAP_0603]  -76.05 76.18 0 top
C357  0.1uf  [CAP_0603]  -51.09 255.32 0 top
C358  0.1uf  [CAP_0603]  -51.09 251.66 0 top
C359  0.001uf  [CAP_0603]  -59.29 93.18 0 top
C360  0.1uf  [CAP_0603]  -51.09 248.01 0 top
C361  0.01uf  [CAP_0603]  -59.29 169.95 0 top
C362  0.01uf  [CAP_0603]  -59.29 166.3 0 top
C363  0.1uf  [CAP_0603]  -51.09 244.35 0 top
C364  2.2uf  [CAP_0805]  -70.02 265.63 0 top
C365  2.2uf  [CAP_0805]  -70.02 261.52 0 top
C366  2.2uf  [CAP_0805]  -70.02 257.41 0 top
C367  0.01uf  [CAP_0603]  -76.05 68.87 0 top
C368  0.01uf  [CAP_0603]  -76.05 65.22 0 top
C369  0.1uf  [CAP_0603]  -51.09 240.7 0 top
C370  0.1uf  [CAP_0603]  -51.09 237.04 0 top
C371  0.1uf  [CAP_0603]  -51.09 233.38 0 top
C372  0.1uf  [CAP_0603]  -51.09 229.73 0 top
C373  0.01uf  [CAP_0603]  -76.05 57.91 0 top
C374  0.1uf  [CAP_0603]  -51.09 226.07 0 top
C375  0.01uf  [CAP_0603]  -76.05 54.25 0 top
C376  0.01uf  [CAP_0603]  -76.05 50.59 0 top
C377  0.1uf  [CAP_0603]  -51.09 222.42 0 top
C378  0.1uf  [CAP_0603]  -51.09 218.76 0 top
C379  0.01uf  [CAP_0603]  -76.05 46.94 0 top
C380  0.1uf  [CAP_0603]  -51.09 215.11 0 top
C381  0.01uf  [CAP_0603]  -76.05 39.63 0 top
C382  0.01uf  [CAP_0603]  -76.05 35.97 0 top
C383  0.01uf  [CAP_0603]  -76.05 32.31 0 top
C384  0.01uf  [CAP_0603]  -76.05 28.66 0 top
C385  0.1uf  [CAP_0603]  -51.09 211.45 0 top
C386  0.01uf  [CAP_0603]  -76.05 25 0 top
C387  0.1uf  [CAP_0603]  -51.09 207.79 0 top
C388  0.1uf  [CAP_0603]  -51.09 54.25 0 top
C389  0.01uf  [CAP_0603]  -76.05 21.35 0 top
C390  0.1uf  [CAP_0603]  -51.09 200.48 0 top
C391  0.01uf  [CAP_0603]  -76.05 14.04 0 top
C392  0.01uf  [CAP_0603]  -76.05 10.38 0 top
C393  0.01uf  [CAP_0603]  -76.05 6.72 0 top
C394  0.1uf  [CAP_0603]  -51.09 196.83 0 top
C395  0.01uf  [CAP_0603]  -76.05 3.07 0 top
C396  0.01uf  [CAP_0603]  -77.9 302.85 0 top
C397  0.01uf  [CAP_0603]  -77.9 299.19 0 top
C398  2.2uf  [CAP_0805]  -70.02 253.3 0 top
C399  2.2uf  [CAP_0805]  -70.02 249.19 0 top
C400  0.01uf  [CAP_0603]  -77.9 291.88 0 top
C401  0.1uf  [CAP_0603]  -51.09 193.17 0 top
C402  0.01uf  [CAP_0603]  -77.9 288.22 0 top
C403  0.1uf  [CAP_0603]  -51.09 189.51 0 top
C404  0.01uf  [CAP_0603]  -77.9 284.57 0 top
C405  0.01uf  [CAP_0603]  -77.9 280.91 0 top
C406  0.01uf  [CAP_0603]  -77.9 277.25 0 top
C407  0.01uf  [CAP_0603]  -77.9 273.6 0 top
C408  0.1uf  [CAP_0603]  -51.09 185.86 0 top
C409  0.1uf  [CAP_0603]  -51.09 182.2 0 top
C410  0.01uf  [CAP_0603]  -77.9 269.94 0 top
C411  2.2uf  [CAP_0805]  -70.02 240.97 0 top
C412  2.2uf  [CAP_0805]  -70.02 236.86 0 top
C413  2.2uf  [CAP_0805]  -70.02 232.75 0 top
C414  0.1uf  [CAP_0603]  -51.09 178.55 0 top
C415  0.1uf  [CAP_0603]  -51.09 174.89 0 top
C416  0.001uf  [CAP_0603]  -59.29 89.53 0 top
C417  0.001uf  [CAP_0603]  -59.29 85.87 0 top
C418  470pf  [CAP_0603]  -91.14 275.41 0 top
C419  0.01uf  [CAP_0603]  -69.7 82.25 0 top
C420  0.01uf  [CAP_0603]  -59.29 158.99 0 top
C421  0.1uf  [CAP_0603]  -51.09 171.24 0 top
C422  0.01uf  [CAP_0603]  -77.9 266.29 0 top
C423  0.01uf  [CAP_0603]  -77.9 262.63 0 top
C424  0.1uf  [CAP_0603]  -51.09 167.58 0 top
C425  1.0uf  [CAP_0805]  -80.07 77.8 0 top
C426  0.1uf  [CAP_0603]  -51.09 163.92 0 top
C427  2.2uf  [CAP_0805]  -70.02 228.64 0 top
C428  2.2uf  [CAP_0805]  -70.02 224.53 0 top
C429  0.1uf  [CAP_0603]  -51.09 160.27 0 top
C430  0.1uf  [CAP_0603]  -51.09 156.61 0 top
C431  0.001uf  [CAP_0603]  -59.29 82.21 0 top
C432  0.001uf  [CAP_0603]  -59.29 78.56 0 top
C433  0.1uf  [CAP_0603]  -51.09 152.96 0 top
C434  0.01uf  [CAP_0603]  -59.29 155.33 0 top
C435  0.001uf  [CAP_0603]  -59.29 74.9 0 top
C436  0.001uf  [CAP_0603]  -59.29 71.25 0 top
C437  0.01uf  [CAP_0603]  -59.29 151.68 0 top
C438  2.2uf  [CAP_0805]  -70.02 220.42 0 top
C439  0.1uf  [CAP_0603]  -51.09 149.3 0 top
C440  0.01uf  [CAP_0603]  -77.9 255.32 0 top
C441  0.01uf  [CAP_0603]  -77.9 251.66 0 top
C442  0.01uf  [CAP_0603]  -77.9 248.01 0 top
C443  0.01uf  [CAP_0603]  -77.9 244.35 0 top
C444  0.01uf  [CAP_0603]  -77.9 240.7 0 top
C445  0.01uf  [CAP_0603]  -77.9 237.04 0 top
C446  0.01uf  [CAP_0603]  -77.9 233.38 0 top
C447  0.1uf  [CAP_0603]  -51.09 141.99 0 top
C448  0.01uf  [CAP_0603]  -77.9 229.73 0 top
C449  0.01uf  [CAP_0603]  -77.9 226.07 0 top
C450  0.01uf  [CAP_0603]  -77.9 222.42 0 top
C451  0.1uf  [CAP_0603]  -51.09 134.68 0 top
C452  0.1uf  [CAP_0603]  -51.09 131.02 0 top
C453  0.01uf  [CAP_0603]  -77.9 218.76 0 top
C454  0.01uf  [CAP_0603]  -77.9 215.11 0 top
C455  0.01uf  [CAP_0603]  -77.9 211.45 0 top
C456  0.01uf  [CAP_0603]  -77.9 207.79 0 top
C457  0.01uf  [CAP_0603]  -77.9 204.14 0 top
C458  0.1uf  [CAP_0603]  -51.09 127.37 0 top
C459  2.2uf  [CAP_0805]  -70.02 216.31 0 top
C460  0.001uf  [CAP_0603]  -59.29 67.59 0 top
C461  0.001uf  [CAP_0603]  -59.29 63.94 0 top
C462  0.001uf  [CAP_0603]  -59.29 60.28 0 top
C463  2.2uf  [CAP_0805]  -70.02 212.2 0 top
C464  0.1uf  [CAP_0603]  -51.09 123.71 0 top
C465  0.01uf  [CAP_0603]  -77.9 196.83 0 top
C466  0.1uf  [CAP_0603]  -51.09 120.05 0 top
C467  0.1uf  [CAP_0603]  -51.09 116.4 0 top
C468  0.01uf  [CAP_0603]  -77.9 193.17 0 top
C469  0.1uf  [CAP_0603]  -51.09 112.74 0 top
C470  0.1uf  [CAP_0603]  -51.09 109.09 0 top
C471  0.01uf  [CAP_0603]  -77.9 189.51 0 top
C472  0.1uf  [CAP_0603]  -51.09 105.43 0 top
C473  0.01uf  [CAP_0603]  -77.9 185.86 0 top
C474  0.01uf  [CAP_0603]  -77.9 182.2 0 top
C475  0.1uf  [CAP_0603]  -51.09 101.77 0 top
C476  0.01uf  [CAP_0603]  -77.9 178.55 0 top
C477  0.1uf  [CAP_0603]  -51.09 98.12 0 top
C478  0.01uf  [CAP_0603]  -77.9 174.89 0 top
C479  0.01uf  [CAP_0603]  -77.9 171.24 0 top
C480  0.1uf  [CAP_0603]  -51.09 94.46 0 top
C481  0.1uf  [CAP_0603]  -51.09 90.81 0 top
C482  0.1uf  [CAP_0603]  -51.09 87.15 0 top
C483  0.01uf  [CAP_0603]  -77.9 167.58 0 top
C484  0.1uf  [CAP_0603]  -51.09 83.5 0 top
C485  0.1uf  [CAP_0603]  -51.09 79.84 0 top
C486  0.01uf  [CAP_0603]  -77.9 163.92 0 top
C487  0.01uf  [CAP_0603]  -77.9 160.27 0 top
C488  0.1uf  [CAP_0603]  -51.09 76.18 0 top
C489  0.01uf  [CAP_0603]  -59.29 148.02 0 top
C490  0.001uf  [CAP_0603]  -59.29 56.62 0 top
C491  0.01uf  [CAP_0603]  -77.9 152.96 0 top
C492  0.01uf  [CAP_0603]  -77.9 149.3 0 top
C493  0.1uf  [CAP_0603]  -51.09 72.53 0 top
C494  0.01uf  [CAP_0603]  -77.9 145.64 0 top
C495  0.1uf  [CAP_0603]  -52.94 39.63 0 top
C496  0.1uf  [CAP_0603]  -51.09 68.87 0 top
C497  0.1uf  [CAP_0603]  -51.09 65.22 0 top
C498  0.1uf  [CAP_0603]  -51.09 61.56 0 top
C499  0.1uf  [CAP_0603]  -51.09 57.91 0 top
C500  0.1uf  [CAP_0603]  -52.94 178.55 0 top
C501  0.1uf  [CAP_0603]  -51.09 50.59 0 top
C502  0.1uf  [CAP_0603]  -51.09 46.94 0 top
C503  0.01uf  [CAP_0603]  -77.9 141.99 0 top
C504  0.01uf  [CAP_0603]  -77.9 138.33 0 top
C505  0.1uf  [CAP_0603]  -51.09 43.28 0 top
C506  0.01uf  [CAP_0603]  -77.9 134.68 0 top
C507  0.01uf  [CAP_0603]  -77.9 131.02 0 top
C508  0.01uf  [CAP_0603]  -77.9 127.37 0 top
C509  0.01uf  [CAP_0603]  -77.9 123.71 0 top
C510  0.01uf  [CAP_0603]  -77.9 120.05 0 top
C511  0.01uf  [CAP_0603]  -77.9 116.4 0 top
C512  0.01uf  [CAP_0603]  -77.9 112.74 0 top
C513  0.1uf  [CAP_0603]  -51.09 39.63 0 top
C514  0.01uf  [CAP_0603]  -77.9 109.09 0 top
C515  0.01uf  [CAP_0603]  -77.9 105.43 0 top
C516  0.01uf  [CAP_0603]  -77.9 101.77 0 top
C517  0.1uf  [CAP_0603]  -51.09 35.97 0 top
C518  0.01uf  [CAP_0402]  -79.57 2.78 0 top
C519  0.001uf  [CAP_0603]  -59.29 52.97 0 top
C520  0.1uf  [CAP_0603]  -51.09 32.31 0 top
C521  0.1uf  [CAP_0603]  -51.09 28.66 0 top
C522  0.1uf  [CAP_0603]  -51.09 25 0 top
C523  0.01uf  [CAP_0603]  -77.9 98.12 0 top
C524  0.01uf  [CAP_0603]  -59.29 144.36 0 top
C525  0.1uf  [CAP_0603]  -51.09 21.35 0 top
C526  0.01uf  [CAP_0402]  -90.96 303.53 0 top
C527  0.01uf  [CAP_0603]  -77.9 94.46 0 top
C528  0.01uf  [CAP_0603]  -77.9 90.81 0 top
C529  0.01uf  [CAP_0603]  -77.9 87.15 0 top
C530  0.01uf  [CAP_0603]  -102.53 215.09 0 top
C531  0.1uf  [CAP_0603]  -51.09 17.69 0 top
C532  0.01uf  [CAP_0402]  -90.96 301.24 0 top
C533  0.01uf  [CAP_0603]  -102.53 123.4 0 top
C534  0.01uf  [CAP_0603]  -77.9 77.55 0 top
C535  0.01uf  [CAP_0603]  -77.9 73.9 0 top
C536  0.1uf  [CAP_0603]  -51.09 14.04 0 top
C537  0.1uf  [CAP_0603]  -51.09 10.38 0 top
C538  0.1uf  [CAP_0603]  -51.09 6.72 0 top
C539  0.01uf  [CAP_0603]  -77.9 70.24 0 top
C540  0.1uf  [CAP_0603]  -52.94 35.97 0 top
C541  0.01uf  [CAP_0603]  -77.9 66.59 0 top
C542  0.01uf  [CAP_0603]  -77.9 62.93 0 top
C543  0.1uf  [CAP_0603]  -52.94 302.85 0 top
C544  0.1uf  [CAP_0603]  -52.94 299.19 0 top
C545  0.01uf  [CAP_0603]  -77.9 59.27 0 top
C546  0.1uf  [CAP_0603]  -52.94 295.53 0 top
C547  0.01uf  [CAP_0603]  -77.9 55.62 0 top
C548  0.01uf  [CAP_0603]  -77.9 51.96 0 top
C549  0.01uf  [CAP_0603]  -77.9 48.31 0 top
C550  0.1uf  [CAP_0603]  -52.94 288.22 0 top
C551  0.1uf  [CAP_0603]  -52.94 284.57 0 top
C552  0.01uf  [CAP_0603]  -77.9 44.65 0 top
C553  0.1uf  [CAP_0603]  -52.94 280.91 0 top
C554  0.01uf  [CAP_0603]  -77.9 41 0 top
C555  0.1uf  [CAP_0603]  -52.94 277.25 0 top
C556  0.01uf  [CAP_0603]  -77.9 37.34 0 top
C557  0.1uf  [CAP_0603]  -52.94 273.6 0 top
C558  0.01uf  [CAP_0603]  -77.9 33.68 0 top
C559  2.2uf  [CAP_0805]  -70.02 203.98 0 top
C560  0.01uf  [CAP_0603]  -77.9 26.37 0 top
C561  0.01uf  [CAP_0603]  -77.9 22.72 0 top
C562  0.1uf  [CAP_0603]  -52.94 269.94 0 top
C563  0.01uf  [CAP_0603]  -77.9 19.06 0 top
C564  10uf  [CAP_1206]  -70.12 172.27 0 top
C565  0.01uf  [CAP_0603]  -77.9 15.4 0 top
C566  0.1uf  [CAP_0603]  -52.94 266.29 0 top
C567  10uf  [CAP_1206]  -70.12 166.98 0 top
C568  0.1uf  [CAP_0603]  -52.94 262.63 0 top
C569  0.01uf  [CAP_0603]  -77.9 11.75 0 top
C570  0.01uf  [CAP_0603]  -77.9 8.09 0 top
C571  0.1uf  [CAP_0603]  -52.94 258.98 0 top
C572  0.1uf  [CAP_0603]  -52.94 255.32 0 top
C573  0.01uf  [CAP_0603]  -77.9 4.44 0 top
C574  0.01uf  [CAP_0603]  -79.75 302.85 0 top
C575  0.01uf  [CAP_0603]  -79.75 299.19 0 top
C576  0.01uf  [CAP_0603]  -79.75 295.53 0 top
C577  0.01uf  [CAP_0603]  -79.75 291.88 0 top
C578  0.1uf  [CAP_0603]  -52.94 251.66 0 top
C579  0.1uf  [CAP_0603]  -52.94 248.01 0 top
C580  0.01uf  [CAP_0603]  -79.75 284.57 0 top
C581  0.1uf  [CAP_0603]  -52.94 244.35 0 top
C582  0.01uf  [CAP_0603]  -79.75 280.91 0 top
C583  0.1uf  [CAP_0603]  -52.94 240.7 0 top
C584  0.1uf  [CAP_0603]  -52.94 237.04 0 top
C585  0.01uf  [CAP_0603]  -79.75 277.25 0 top
C586  2.2uf  [CAP_0805]  -70.02 199.87 0 top
C587  0.01uf  [CAP_0603]  -102.53 207.78 0 top
C588  0.1uf  [CAP_0603]  -102.53 193.15 0 top
C589  0.01uf  [CAP_0603]  -79.75 273.6 0 top
C590  0.1uf  [CAP_0603]  -52.94 233.38 0 top
C591  0.1uf  [CAP_0603]  -52.94 229.73 0 top
C592  0.01uf  [CAP_0603]  -79.75 266.29 0 top
C593  0.1uf  [CAP_0603]  -52.94 226.07 0 top
C594  0.01uf  [CAP_0603]  -79.75 262.63 0 top
C595  0.01uf  [CAP_0603]  -79.75 258.98 0 top
C596  0.1uf  [CAP_0603]  -52.94 222.42 0 top
C597  0.01uf  [CAP_0603]  -79.75 255.32 0 top
C598  0.01uf  [CAP_0603]  -79.75 251.66 0 top
C599  0.1uf  [CAP_0603]  -52.94 218.76 0 top
C600  0.01uf  [CAP_0603]  -79.75 248.01 0 top
C601  0.1uf  [CAP_0603]  -52.94 215.11 0 top
C602  0.1uf  [CAP_0603]  -52.94 211.45 0 top
C603  0.01uf  [CAP_0603]  -79.75 244.35 0 top
C604  0.1uf  [CAP_0603]  -52.94 207.79 0 top
C605  0.1uf  [CAP_0603]  -52.94 204.14 0 top
C606  0.01uf  [CAP_0603]  -79.75 240.7 0 top
C607  0.01uf  [CAP_0603]  -79.75 237.04 0 top
C608  0.1uf  [CAP_0603]  -52.94 200.48 0 top
C609  0.01uf  [CAP_0603]  -79.75 233.38 0 top
C610  0.1uf  [CAP_0603]  -52.94 196.83 0 top
C611  0.01uf  [CAP_0603]  -79.75 226.07 0 top
C612  0.01uf  [CAP_0603]  -79.75 222.42 0 top
C613  0.1uf  [CAP_0603]  -52.94 193.17 0 top
C614  0.01uf  [CAP_0603]  -102.53 110.6 0 top
C615  0.1uf  [CAP_0603]  -52.94 189.51 0 top
C616  2.2uf  [CAP_0805]  -70.02 195.76 0 top
C617  0.01uf  [CAP_0603]  -79.75 215.11 0 top
C618  0.01uf  [CAP_0603]  -79.75 211.45 0 top
C619  0.01uf  [CAP_0603]  -79.75 207.79 0 top
C620  0.1uf  [CAP_0603]  -52.94 185.86 0 top
C621  0.01uf  [CAP_0603]  -79.75 204.14 0 top
C622  0.01uf  [CAP_0603]  -79.75 200.48 0 top
C623  0.01uf  [CAP_0603]  -79.75 196.83 0 top
C624  0.01uf  [CAP_0603]  -79.75 193.17 0 top
C625  0.01uf  [CAP_0603]  -79.75 189.51 0 top
C626  0.1uf  [CAP_0603]  -59.29 162.64 0 top
C627  2.2uf  [CAP_0805]  -70.02 191.65 0 top
C628  0.01uf  [CAP_0603]  -79.75 185.86 0 top
C629  0.01uf  [CAP_0603]  -79.75 182.2 0 top
C630  0.01uf  [CAP_0603]  -79.75 178.55 0 top
C631  0.01uf  [CAP_0603]  -79.75 174.89 0 top
C632  0.01uf  [CAP_0603]  -79.75 171.24 0 top
C633  0.01uf  [CAP_0603]  -79.75 167.58 0 top
C634  0.01uf  [CAP_0603]  -79.75 163.92 0 top
C635  0.01uf  [CAP_0603]  -79.75 160.27 0 top
C636  0.1uf  [CAP_0603]  -52.94 182.2 0 top
C637  0.01uf  [CAP_0603]  -79.75 156.61 0 top
C638  10pf  [CAP_0603]  -91.14 223.04 0 top
C639  0.01uf  [CAP_0603]  -102.53 211.43 0 top
C640  0.1uf  [CAP_0603]  -102.53 196.81 0 top
C641  0.01uf  [CAP_0603]  -79.75 218.76 0 top
C642  0.1uf  [CAP_0603]  -102.53 200.46 0 top
C643  0.1uf  [CAP_0603]  -91.14 219.39 0 top
C644  0.1uf  [CAP_0603]  -91.14 212.07 0 top
C645  0.1uf  [CAP_0603]  -91.14 208.42 0 top
C646  0.1uf  [CAP_0603]  -91.14 204.76 0 top
C647  0.1uf  [CAP_0603]  -91.14 215.73 0 top
C648  0.1uf  [CAP_0603]  -91.14 201.11 0 top
C649  0.01uf  [CAP_0603]  -91.14 197.45 0 top
C650  0.01uf  [CAP_0603]  -91.14 193.79 0 top
C651  0.1uf  [CAP_0603]  -91.14 190.14 0 top
C652  0.1uf  [CAP_0603]  -91.14 182.83 0 top
C653  0.1uf  [CAP_0603]  -91.14 175.52 0 top
C654  0.1uf  [CAP_0603]  -59.29 17.88 0 top
C655  0.1uf  [CAP_0603]  -91.14 179.17 0 top
C656  0.1uf  [CAP_0603]  -91.14 186.48 0 top
C657  0.1uf  [CAP_0603]  -91.14 171.86 0 top
C658  0.01uf  [CAP_0603]  -59.29 140.71 0 top
C659  0.1uf  [CAP_0603]  -52.94 174.89 0 top
C660  0.1uf  [CAP_0603]  -52.94 171.24 0 top
C661  0.1uf  [CAP_0603]  -52.94 167.58 0 top
C662  0.1uf  [CAP_0603]  -52.94 163.92 0 top
C663  0.1uf  [CAP_0603]  -52.94 160.27 0 top
C664  0.1uf  [CAP_0603]  -52.94 156.61 0 top
C665  0.1uf  [CAP_0603]  -52.94 152.96 0 top
C666  0.1uf  [CAP_0603]  -52.94 149.3 0 top
C667  0.01uf  [CAP_0402]  -90.96 165.23 0 top
C668  0.01uf  [CAP_0402]  -90.96 162.95 0 top
C669  0.1uf  [CAP_0603]  -91.14 153.12 0 top
C670  0.1uf  [CAP_0603]  -91.14 149.46 0 top
C671  0.01uf  [CAP_0603]  -91.14 138.49 0 top
C672  0.1uf  [CAP_0603]  -91.14 145.81 0 top
C673  0.01uf  [CAP_0402]  -90.96 160.66 0 top
C674  0.1uf  [CAP_0603]  -91.14 142.15 0 top
C678  10uf  [CAPT_3528]  -55.19 6.08 0 top
C679  10uf  [CAPT_3528]  -61.54 302.51 0 top
C680  47uf  [CAPT_7343]  -84.03 51.19 0 top
C681  1uf  [CAP_0805]  -59.61 225.93 0 top
C682  1uf  [CAP_0805]  -59.61 221.82 0 top
C683  1uf  [CAP_0805]  -59.61 217.71 0 top
C684  0.1uf  [CAP_0603]  -59.29 269.63 0 top
C685  0.1uf  [CAP_0603]  -59.29 265.97 0 top
C686  10uf  [CAPT_3528]  -93.39 134.51 0 top
C687  10uf  [CAPT_3528]  -93.39 130.19 0 top
C688  10uf  [CAPT_3528]  -61.54 298.2 0 top
C689  10uf  [CAPT_3528]  -61.54 293.88 0 top
C690  10uf  [CAPT_3528]  -93.39 125.87 0 top
C691  0.1uf  [CAP_0603]  -59.29 262.31 0 top
C692  0.1uf  [CAP_0603]  -59.29 258.66 0 top
C693  10uf  [CAPT_3528]  -93.39 121.55 0 top
C694  0.1uf  [CAP_0603]  -59.29 255 0 top
C695  10uf  [CAPT_3528]  -93.39 117.24 0 top
C696  47uf  [CAPT_3528]  -93.39 112.92 0 top
C697  47uf  [CAPT_3528]  -93.39 108.6 0 top
C698  220uf  [CAPT_7343]  -95.42 70.25 0 top
C699  220uf  [CAPT_7343]  -95.42 64.4 0 top
C700  220uf  [CAPT_7343]  -95.42 58.56 0 top
C701  220uf  [CAPT_7343]  -95.42 52.72 0 top
C702  0.1uf  [CAP_0603]  -52.94 145.64 0 top
C703  0.1uf  [CAP_0603]  -52.94 141.99 0 top
C706  0.1uf  [CAP_0603]  -52.94 138.33 0 top
C711  0.001uf  [CAP_0402]  -90.96 48.66 0 top
C712  0.001uf  [CAP_0402]  -90.96 46.37 0 top
C713  0.001uf  [CAP_0402]  -90.96 44.08 0 top
C714  100uf  [CAPT_C]  -106.18 114.72 0 top
C715  0.1uf  [CAP_0603]  -52.94 134.68 0 top
C716  100uf  [CAPT_7343]  -106.18 219.2 0 top
C717  100uf  [CAPT_7343]  -106.18 119.29 0 top
C718  0.1uf  [CAP_0603]  -52.94 131.02 0 top
C719  0.1uf  [CAP_0603]  -52.94 127.37 0 top
C720  0.1uf  [CAP_0603]  -52.94 123.71 0 top
C721  0.1uf  [CAP_0603]  -52.94 120.05 0 top
C722  0.1uf  [CAP_0603]  -52.94 116.4 0 top
C725  0.01uf  [CAP_0402]  -102.35 160.66 0 top
C726  0.1uf  [CAP_0603]  -52.94 112.74 0 top
C727  47uf  [CAPT_3528]  -93.39 104.28 0 top
C728  0.01uf  [CAP_0603]  -79.75 131.02 0 top
C729  47uf  [CAPT_3528]  -93.39 99.96 0 top
C730  0.01uf  [CAP_0603]  -79.75 127.37 0 top
C731  47uf  [CAPT_3528]  -93.39 95.65 0 top
C732  0.01uf  [CAP_0603]  -79.75 123.71 0 top
C733  0.1uf  [CAP_0603]  -52.94 109.09 0 top
C734  47uf  [CAPT_3528]  -93.39 91.33 0 top
C735  0.1uf  [CAP_0603]  -52.94 105.43 0 top
C736  47uf  [CAPT_3528]  -93.39 87.01 0 top
C745  0.1uf  [CAP_0603]  -91.14 168.2 0 top
C746  0.1uf  [CAP_0603]  -52.94 101.77 0 top
C747  0.1uf  [CAP_0603]  -52.94 98.12 0 top
C748  0.1uf  [CAP_0603]  -52.94 94.46 0 top
C749  0.1uf  [CAP_0603]  -52.94 90.81 0 top
C750  0.1uf  [CAP_0603]  -52.94 87.15 0 top
C751  0.1uf  [CAP_0603]  -52.94 83.5 0 top
C752  0.01uf  [CAP_0402]  -90.96 158.37 0 top
C753  0.01uf  [CAP_0402]  -90.96 156.09 0 top
C754  470pf  [CAP_0402]  -90.96 6.75 0 top
C755  0.001uf  [CAP_0402]  -102.35 234.51 0 top
C756  0.1uf  [CAP_0402]  -90.96 289.81 0 top
C757  2.2uf  [CAPT_0603]  -102.53 293.7 0 top
C758  470pf  [CAP_0402]  -90.96 4.46 0 top
C759  0.001uf  [CAP_0402]  -102.35 236.8 0 top
C760  0.1uf  [CAP_0402]  -90.96 287.53 0 top
C761  2.2uf  [CAPT_0603]  -102.53 290.05 0 top
C762  470pf  [CAP_0402]  -90.96 2.17 0 top
C763  0.001uf  [CAP_0402]  -102.35 239.09 0 top
C764  0.1uf  [CAP_0402]  -90.96 285.24 0 top
C765  2.2uf  [CAPT_0603]  -102.53 286.39 0 top
C766  470pf  [CAP_0402]  -102.35 303.53 0 top
C767  0.001uf  [CAP_0402]  -102.35 241.37 0 top
C768  0.1uf  [CAP_0402]  -90.96 282.96 0 top
C769  2.2uf  [CAPT_0603]  -102.53 282.73 0 top
C770  470pf  [CAP_0402]  -102.35 301.24 0 top
C771  0.001uf  [CAP_0402]  -102.35 243.66 0 top
C772  0.1uf  [CAP_0402]  -90.96 280.67 0 top
C773  2.2uf  [CAPT_0603]  -102.53 279.08 0 top
C774  0.001uf  [CAP_0603]  -102.53 271.77 0 top
C775  470pf  [CAP_0402]  -102.35 298.96 0 top
C776  2.2uf  [CAP_0805]  -70.02 187.54 0 top
C777  1.0uf  [CAP_0805]  -80.07 73.69 0 top
C778  470pf  [CAP_0402]  -102.35 296.67 0 top
C779  0.001uf  [CAP_0402]  -102.35 245.94 0 top
C780  0.1uf  [CAP_0402]  -90.96 278.38 0 top
C781  2.2uf  [CAPT_0603]  -102.53 275.42 0 top
C782  100uf  [CAPT_7343]  -95.42 40.02 0 top
C783  100uf  [CAPT_7343]  -95.42 34.18 0 top
C784  100uf  [CAPT_7343]  -95.42 28.34 0 top
C785  100uf  [CAPT_7343]  -95.42 22.49 0 top
C786  220uf  [CAPT_7343]  -95.42 81.93 0 top
C787  220uf  [CAPT_7343]  -95.42 76.09 0 top
C788  100uf  [CAPT_7343]  -95.42 16.65 0 top
C789  100uf  [CAPT_7343]  -95.42 10.81 0 top
C790  1.0uf  [CAP_0805]  -80.07 94.24 0 top
CN1  0.1uf  [8_PINS_SURFACE_MOUNT]  -155.7 241.05 0 top
